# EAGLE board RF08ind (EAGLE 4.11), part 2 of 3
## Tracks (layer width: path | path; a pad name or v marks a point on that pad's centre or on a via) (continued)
DMA02  (via drill 0.61) (continued)
  Top 0.254: DMA0-3.2 25.39,125.56 24.12,126.83 24.12,149.7 25.39,150.97 IC38.4 | v16.51,205.58 2.54,191.61 v2.54,154.78 | v67.31,19.52 v67.31,31.59 | v141.6,16.35 145.41,20.16 145.41,151.6 146.68,152.87 v146.68,206.84
  Bottom 0.254: 146.68,207.48 114.93,207.48 112.39,204.94 80.64,204.94 80.01,205.58 v16.51,205.58 | v2.54,154.78 8.25,149.06 8.88,149.7 15.87,149.7 16.51,150.33 23.49,150.33 24.76,151.6 IC38.4 | v67.31,31.59 65.4,31.59 64.13,32.86 RS08.14 | v67.31,19.52 67.94,20.16 73.66,20.16 74.29,20.79 114.93,20.79 118.11,23.96 128.27,23.96 130.81,21.43 133.34,21.43 138.43,16.35 v141.6,16.35 | 146.68,207.48 v146.68,206.84 | 146.68,207.48 165.73,207.48 167,206.21 IC27.13
DMA03  (via drill 0.61)
  Top 0.254: v29.21,126.2 30.48,127.47 30.48,150.97 IC38.2 | v192.4,91.91 191.77,92.54 189.22,95.08 189.22,154.78 189.86,155.41 189.86,193.51 v198.75,202.4 | v183.51,83.02 v154.3,53.81 | v67.31,44.92 67.31,35.4 66.04,34.12 66.04,33.49 RS08.12 | v20.32,120.48 19.68,119.85 19.68,98.26 15.87,94.45 v15.87,51.27
  Bottom 0.254: v29.21,126.2 24.76,126.2 23.49,124.93 DMA0-3.3 22.86,123.02 v20.32,120.48 | v183.51,83.02 v192.4,91.91 | v154.3,53.81 144.78,44.29 138.43,44.29 137.79,44.92 137.79,51.91 90.17,51.91 83.18,44.92 v67.31,44.92 66.04,44.92 65.4,44.29 34.92,44.29 33.65,45.55 21.59,45.55 v15.87,51.27 | v198.75,202.4 199.38,201.77 212.09,201.77 215.26,204.94 IC39.9
DMA04  (via drill 0.61)
  Top 0.254: v38.73,126.2 38.09,126.83 v38.09,152.24 | RS08.9 68.58,29.68 69.84,28.41 v69.84,11.27 69.84,1.74 142.87,1.74 191.13,50 194.31,53.18 194.31,87.46 v201.93,95.08 | v23.49,121.75 22.22,120.48 22.22,114.77 22.86,114.13 22.86,82.38 20.32,79.84 20.32,25.23 v25.39,20.16 | v212.09,176.37 212.09,203.03 210.81,204.31 IC39.11 | v190.5,99.53 v190.5,154.78
  Bottom 0.254: v38.09,152.24 40,154.14 43.81,154.14 45.08,152.87 IC31.8 | DMA4-7.7 42.54,124.93 41.27,126.2 v38.73,126.2 35.55,123.02 29.21,123.02 27.94,121.75 v23.49,121.75 | v25.39,20.16 29.21,16.35 29.21,11.27 v69.84,11.27 | v190.5,154.78 v212.09,176.37 | v190.5,99.53 194.94,95.08 v201.93,95.08
DMA05  (via drill 0.61)
  Top 0.254: IC31.6 50.79,150.97 52.06,149.7 52.06,144.62 49.52,142.08 49.52,138.27 50.16,137.63 50.16,136.36 46.98,133.19 46.98,126.83 45.71,125.56 DMA4-7.6 45.71,123.02 v45.71,121.12 | 95.25,7.46 147.31,7.46 190.5,50.63 190.5,86.19 193.67,89.37 193.67,91.91 191.77,93.81 191.77,194.15 v200.66,203.03 | 95.25,7.46 v95.25,27.78 | v90.8,3.01 95.25,7.46
  Bottom 0.254: v95.25,27.78 93.98,29.05 67.94,29.05 66.67,30.32 RS08.11 | v45.71,121.12 44.45,119.85 24.12,119.85 23.49,119.21 15.23,119.21 11.42,115.4 7.62,115.4 5.71,113.5 5.71,5.55 39.36,5.55 41.9,3.01 v90.8,3.01 | v200.66,203.03 203.19,203.03 205.1,204.94 IC39.13
DMA06  (via drill 0.61)
  Top 0.254: DMA4-7.2 55.88,125.56 54.6,126.83 54.6,149.7 55.88,150.97 IC31.4 | 188.59,91.27 189.86,92.54 | 188.59,91.27 v170.18,72.86 | v120.01,56.35 116.84,53.18 v116.84,46.83 | v66.04,43.65 64.13,41.74 64.13,36.03 62.22,34.12 62.22,32.22 63.49,30.95 RS08.13 | v23.49,120.48 23.49,81.75 21.59,79.84 v21.59,44.29 | 188.59,91.27 v188.59,185.25
  Bottom 0.254: v170.18,72.86 154.94,57.62 121.28,57.62 v120.01,56.35 | v116.84,46.83 86.99,46.83 83.81,43.65 v66.04,43.65 34.28,43.65 33.02,44.92 22.22,44.92 v21.59,44.29 | v23.49,120.48 27.94,120.48 29.84,122.39 53.97,122.39 55.24,123.66 DMA4-7.2 | v188.59,185.25 187.32,186.53 188.59,187.8 226.69,187.8 241.3,202.4 250.82,202.4 253.36,204.94 IC43.9
DMA07  (via drill 0.61)
  Top 0.254: IC31.2 60.95,150.97 60.95,127.47 v59.68,126.2 59.68,112.23 | v188.59,186.53 187.32,185.25 187.32,91.27 v170.18,74.13 | v129.53,62.06 123.82,62.06 v123.82,72.22 | v80.64,69.68 81.28,70.32 81.28,81.75 80.01,83.02 80.01,108.42 79.37,109.05 79.37,109.69 v80.01,110.32 | v60.32,111.59 59.68,112.23 | 59.68,112.23 59.68,69.68 60.95,68.41 60.95,36.66 59.68,35.4 59.68,32.22 60.95,30.95 RS08.15 | v248.91,201.13 248.91,204.31 IC43.11
  Bottom 0.254: v59.68,126.2 55.24,126.2 53.97,124.93 DMA4-7.3 | v248.91,201.13 234.31,186.53 v188.59,186.53 | v170.18,74.13 150.49,74.13 140.97,64.6 135.88,64.6 133.34,62.06 v129.53,62.06 | v123.82,72.22 121.28,74.77 118.11,74.77 113.03,69.68 v80.64,69.68 | v80.01,110.32 78.73,111.59 v60.32,111.59
DMA08  (via drill 0.61)
  Top 0.254: v67.94,126.2 68.58,126.83 68.58,138.27 67.31,139.53 67.31,140.17 67.94,140.81 v67.94,151.6 67.94,159.22 72.39,163.67 72.39,200.5 v74.93,203.03 | v57.14,53.81 57.14,32.22 58.41,30.95 RS08.17 | v78.1,55.08 78.73,55.72 78.73,93.81 77.47,95.08 73.02,95.08 73.02,112.86 72.39,113.5 72.39,119.85 73.66,121.12 73.66,123.02 DMA8-11.7
  Bottom 0.254: v67.94,126.2 71.75,126.2 73.02,124.93 DMA8-11.7 | v67.94,151.6 70.48,154.14 74.29,154.14 75.56,152.87 IC24.8 | v74.93,203.03 80.01,203.03 80.64,203.67 180.97,203.67 184.78,207.48 241.93,207.48 243.2,206.21 IC43.13 | v57.14,53.81 59.05,55.72 77.47,55.72 v78.1,55.08
DMA09  (via drill 0.61)
  Top 0.254: 82.55,130.65 76.83,124.93 DMA8-11.6 | 82.55,130.65 82.55,149.7 81.28,150.97 IC24.6 81.28,153.5 80.01,154.78 v80.01,204.31 | v159.38,202.4 v156.84,204.94 | v54.6,45.55 54.6,32.22 55.88,30.95 RS08.19 | v76.2,46.83 82.55,53.18 82.55,87.46 81.91,88.1 81.91,110.96 82.55,111.59 82.55,130.65 | v194.94,202.4 204.47,211.93 204.47,214.47 201.93,217 201.93,220.81 287.01,220.81 293.37,214.47 293.37,208.12 292.1,206.84 IC45.9
  Bottom 0.254: v156.84,204.94 156.21,204.31 v80.01,204.31 | v54.6,45.55 55.88,46.83 v76.2,46.83 | v194.94,202.4 v159.38,202.4
DMA10  (via drill 0.61)
  Top 0.254: 85.09,149.7 85.09,126.83 86.36,125.56 DMA8-11.2 86.36,123.02 83.81,120.48 83.81,110.32 83.18,109.69 83.18,89.37 83.81,88.73 83.81,49.37 v85.09,48.09 | 85.09,149.7 86.36,150.97 IC24.4 | v97.15,210.66 85.09,198.59 85.09,149.7 | v52.06,45.55 52.06,32.22 53.34,30.95 RS08.21
  Bottom 0.254: v52.06,45.55 54.6,48.09 v85.09,48.09 | v97.15,210.66 103.5,210.66 105.41,208.75 283.84,208.75 286.38,206.21 IC45.11
DMA11  (via drill 0.61)
  Top 0.254: v97.79,128.11 97.15,128.74 97.15,153.5 v97.79,154.14 97.79,163.03 100.96,166.21 100.96,183.35 100.33,183.99 v100.33,199.86 | v81.28,25.23 81.28,50.63 83.18,52.54 83.18,88.1 82.55,88.73 82.55,110.32 83.18,110.96 83.18,123.66 DMA8-11.3 | v284.48,201.13 284.48,201.77 281.94,204.31 IC45.13
  Bottom 0.254: v97.79,128.11 87.62,128.11 84.45,124.93 DMA8-11.3 | v97.79,154.14 93.34,154.14 92.07,152.87 IC24.2 | v284.48,201.13 267.33,183.99 188.59,183.99 172.08,200.5 151.12,200.5 150.49,201.13 147.95,201.13 147.31,200.5 100.96,200.5 v100.33,199.86 | v81.28,25.23 76.2,25.23 74.29,27.14 61.59,27.14 59.68,29.05 59.68,30.95 59.05,31.59 52.7,31.59 51.43,30.32 RS08.23
DMA-IN\  (via drill 0.61)
  Top 0.254: IC26.1 78.73,16.35 78.73,18.89 76.2,21.43 IC26.19 76.2,23.96 72.39,27.78 v72.39,37.94 | IC41.12 18.41,85.56 19.68,84.29 19.68,16.35 29.84,6.18 44.45,6.18 44.45,10.63 45.08,11.27 48.25,11.27 48.25,13.81 IC34.1
  Bottom 0.254: IC34.1 48.89,14.44 50.16,13.17 76.83,13.17 78.1,14.44 IC26.1 | v72.39,37.94 102.87,37.94 IC13.4
DMA-OUT\
  Top 0.254: IC35.1 45.71,72.22 43.17,74.77 43.17,77.3 IC35.19
  Bottom 0.254: IC28.19 70.48,77.94 69.21,76.67 45.08,76.67 43.81,77.94 IC35.19 42.54,79.21 41.27,80.48 22.86,80.48 22.86,88.73 18.41,93.18 IC41.9 | IC28.1 73.02,70.32 71.75,69.05 47.62,69.05 46.35,70.32 IC35.1
DONE  (via drill 0.61)
  Top 0.254: v3.81,143.98 3.81,191.61 v19.05,206.84 | v112.39,206.21 125.73,192.88 125.73,176.37 125.09,175.73 125.09,174.46 126.36,173.19 IC11.9 | v280.67,122.39 280.67,93.81 281.94,92.54 IC46.13
  Bottom 0.254: v3.81,143.98 4.44,143.34 12.69,143.34 14.6,141.44 20.95,141.44 22.22,140.17 IC40.2 | v19.05,206.84 19.68,206.21 v112.39,206.21 | v280.67,122.39 252.09,150.97 168.27,150.97 160.65,158.59 158.75,158.59 146.05,171.28 129.53,171.28 128.27,172.56 IC11.9
DRV01\  (via drill 0.61)
  Top 0.254: v18.41,38.57 13.33,43.65 13.33,80.48 10.79,83.02 IC41.4
  Bottom 0.254: v18.41,38.57 19.05,39.2 26.03,39.2 32.38,32.86 RS08.38
DRV23\  (via drill 0.61)
  Top 0.254: v14.6,66.51 14.6,86.83 10.79,90.64 IC41.7 | v50.79,62.06 53.34,59.52 53.34,33.49 RS08.22
  Bottom 0.254: v14.6,66.51 19.05,62.06 v50.79,62.06
DRVOK\  (via drill 0.61)
  Top 0.254: IC21.13 95.88,80.48 95.88,79.21 IC21.14 97.15,77.94 98.42,76.67 98.42,56.35 97.15,55.08 v97.15,45.55 | v30.48,43.65 30.48,33.49 RS08.40
  Bottom 0.254: R2.1 25.39,37.3 29.84,32.86 RS08.40 | v97.15,45.55 93.98,42.38 48.89,42.38 48.25,43.02 31.11,43.02 v30.48,43.65
EIE  (via drill 0.61)
  Top 0.254: IC40.9 12.69,148.43 11.42,149.7 11.42,173.83 14.6,177 INTENB.6 | v93.34,105.24 92.7,105.88 92.7,133.82 v93.34,134.46
  Bottom 0.254: v93.34,105.24 128.27,105.24 130.81,102.7 133.34,102.7 138.43,97.62 140.97,97.62 144.14,94.45 169.54,94.45 172.08,91.91 IC33.11 | v93.34,134.46 8.88,134.46 1.9,141.44 1.9,148.43 8.88,148.43 9.52,149.06 10.79,149.06 12.06,147.79 IC40.9 | IC37.2 32.38,187.16 29.21,183.99 13.96,183.99 13.33,183.35 13.33,178.27 14.6,178.27 INTENB.6
ERROR  (via drill 0.61)
  Top 0.254: v36.82,173.83 v36.82,145.25 | v95.88,173.83 96.52,174.46 v96.52,183.99 | v127,182.72 128.9,180.81 128.9,163.03 131.44,160.49 IC7.2
  Bottom 0.254: v36.82,145.25 17.14,145.25 15.87,146.52 IC40.10 | v95.88,173.83 v36.82,173.83 | v96.52,183.99 97.15,184.62 103.5,184.62 106.04,187.16 IC12.6 107.31,187.16 111.12,183.35 126.36,183.35 v127,182.72
EXAD0\
  Top 0.254: IC20.9 88.9,13.81 84.45,9.36 84.45,6.82 83.18,5.55 71.12,5.55 71.12,6.82 C35L.34
EXAD1\
  Top 0.254: IC20.7 93.34,15.71 92.07,16.98 83.81,16.98 83.81,7.46 82.55,6.18 73.66,6.18 73.66,6.82 C35L.36
EXAD2\
  Bottom 0.254: IC20.5 98.42,14.44 92.7,8.73 78.1,8.73 76.83,7.46 C35L.38
F.1  (via drill 0.61)
  Top 0.254: IC20.11 86.99,22.06 88.26,20.79 92.7,20.79 92.7,47.46 92.07,48.09 92.07,93.81 94.61,96.35 94.61,99.53 95.25,100.16 99.06,100.16 99.06,126.2 100.33,127.47 100.33,138.9 100.96,139.53 100.96,151.6 101.59,152.24 v101.59,185.89 v101.59,213.83 | v49.52,192.24 49.52,190.34 48.25,189.06 IC30.8 | v86.36,192.88 88.9,190.34 88.9,189.06 FIELD.3
  Bottom 0.254: v101.59,185.89 90.8,185.89 89.53,187.16 FIELD.3 | v49.52,192.24 50.16,192.88 v86.36,192.88 | v101.59,213.83 144.78,213.83 146.05,215.1 173.35,215.1 174.62,213.83 IC27.5
F.2  (via drill 0.61)
  Top 0.254: 90.17,185.25 90.17,150.97 91.44,149.7 91.44,23.96 IC20.13 | 90.17,185.25 91.44,186.53 FIELD.2 | 90.17,185.25 v90.17,197.32 90.17,202.4 v99.69,211.93
  Bottom 0.254: v90.17,197.32 45.08,197.32 43.81,196.05 IC30.11 | v99.69,211.93 100.33,211.29 168.27,211.29 169.54,212.56 IC27.3
F.3  (via drill 0.61)
  Top 0.254: v81.28,191.61 81.28,189.06 FIELD.6 | v48.25,190.97 48.25,194.15 IC30.13 | IC20.15 97.15,22.06 102.87,16.35 102.87,13.81 108.58,8.09 146.68,8.09 146.68,101.43 148.59,103.34 148.59,121.75 150.49,123.66 v150.49,199.86 150.49,212.56 164.46,212.56 IC27.1
  Bottom 0.254: v48.25,190.97 49.52,190.97 50.79,192.24 80.64,192.24 v81.28,191.61 93.34,191.61 101.59,199.86 v150.49,199.86
GND  (via drill 0.61)
  Top 0.508: IC4.8 131.44,103.34 131.44,102.07 IC4.7 132.71,100.8 133.98,99.53 133.98,74.13 | IC2.7 131.44,51.27 131.44,52.54 IC2.8 132.71,53.81 133.98,55.08 133.98,74.13 | IC3.8 131.44,77.94 131.44,76.67 IC3.7 132.71,75.4 133.98,74.13 | J14.2 27.94,171.92 27.94,170.65 D34L.1 | J13.2 30.48,171.92 30.48,170.65 D34L.3 | D34L.5 33.02,170.65 33.02,171.92 J12.2 33.02,173.19 34.28,174.46 34.28,182.72 | J11.2 35.55,171.92 35.55,170.65 D34L.7 | J10.2 38.09,171.92 38.09,170.65 D34L.9 | J9.2 40.63,171.92 40.63,170.65 D34L.11 | J8.2 43.17,171.92 43.17,170.65 D34L.13 | J6.2 48.25,171.92 48.25,170.65 D34L.17 | IC37.10 12.69,186.53 12.69,185.25 14.6,183.35 INTENB.8 14.6,182.08 10.15,177.64 10.15,161.12 IC38.11 10.15,158.59 10.15,153.5 IC38.10 10.15,150.97 10.15,150.33 8.88,149.06 8.88,142.08 10.15,140.81 IC40.7 10.15,138.27 8.88,137 8.88,126.83 10.15,125.56 DMA0-3.8 10.15,123.02 10.15,117.31 IC23.7 10.79,116.04 12.06,114.77 12.06,102.07 | INTENB.4 14.6,173.19 14.6,174.46 INTENB.5 | IC37.6 22.86,186.53 22.86,183.35 INTENB.9 | 34.28,182.72 33.65,182.72 C36L.5 | 34.28,182.72 34.92,182.72 C36L.7 | C36L.39 76.2,183.35 76.2,186.53 FIELD.8 76.2,189.06 76.2,194.15 FIELD.9 | IC30.10 43.17,186.53 43.17,183.35 C36L.13 | IC30.6 53.34,186.53 53.34,183.35 C36L.21 | C36L.31 65.4,182.72 64.13,182.72 C36L.29 | IC16.8 104.14,112.23 104.14,118.58 IC17.1 | IC9.7 120.01,124.93 121.28,126.2 121.28,135.09 120.01,136.36 IC10.2 120.01,137.63 121.28,138.9 121.28,147.79 120.01,149.06 IC10.7 | 104.14,173.83 104.14,186.53 IC12.7 | 104.14,173.83 104.14,160.49 IC18.7 | C1.2 139.06,187.8 137.79,187.8 IC8.1 137.16,186.53 137.79,185.89 137.79,161.76 139.06,160.49 IC7.15
  Top 0.508: IC6.8 131.44,150.33 131.44,156.68 IC7.1 132.71,157.95 133.98,159.22 133.98,173.19 132.71,174.46 IC7.8 | 104.14,173.83 118.11,173.83 118.11,175.09 IC11.7 | IC36.8 24.76,109.69 24.12,110.32 24.12,114.77 25.39,116.04 D36L.1 | D36L.7 32.38,116.67 31.11,116.67 D36L.5 | IC32.5 43.81,102.07 45.08,103.34 45.08,107.15 43.81,108.42 IC32.8 42.54,109.69 41.9,110.32 41.9,116.67 | DMA4-7.8 40.63,123.02 40.63,117.31 D36L.13 41.27,116.67 41.9,116.67 | 41.9,116.67 42.54,116.67 D36L.15 | D36L.17 46.35,116.67 47.62,116.67 D36L.19 48.89,116.67 50.16,116.67 D36L.21 50.79,117.31 50.79,123.02 DMA4-7.4 50.79,125.56 52.06,126.83 52.06,137 50.79,138.27 DAR4-7.4 | IC24.10 71.12,150.97 69.84,149.7 69.84,143.34 71.12,142.08 71.12,140.81 DAR8-11.8 | IC31.10 40.63,150.97 41.9,149.7 41.9,144.62 41.27,143.98 41.27,140.17 DAR4-7.8 | DMA8-11.8 71.12,123.02 71.12,117.31 D36L.37 | D36L.25 55.24,116.67 53.97,116.67 D36L.23 | D36L.33 65.4,116.67 64.13,116.67 D36L.31 | v68.58,139.53 69.21,138.9 69.21,116.67 D36L.35 | IC1.7 131.44,25.87 131.44,27.14 IC1.8 130.81,27.78 v127,31.59 | IC20.17 101.59,23.96 103.5,25.87 103.5,29.68 IC13.1 103.5,30.95 103.5,32.22 IC13.2 104.77,33.49 106.04,34.76 106.04,43.65 104.77,44.92 IC13.7 103.5,46.19 103.5,50 IC14.1 103.5,51.27 103.5,52.54 IC14.2 104.77,53.81 106.04,55.08 106.04,56.35 | IC16.1 103.5,93.18 103.5,86.83 IC15.7 104.77,85.56 106.04,84.29 106.04,76.67 | 106.04,56.35 104.77,57.62 IC14.4 | 106.04,63.97 104.77,65.24 IC14.7 | 106.04,63.97 106.04,56.35 | 106.04,76.67 104.77,77.94 IC15.4 | 106.04,76.67 106.04,63.97 | IC26.10 55.88,13.81 55.88,10.63 C35L.21 55.24,10 53.97,10 C35L.19
  Top 0.508: C35L.35 74.29,10 75.56,10 C35L.37 76.83,10 78.1,10 C35L.39 | J2.2 58.41,5.55 57.14,6.82 57.14,8.09 58.41,9.36 C35L.23 | IC34.10 25.39,16.35 26.67,17.62 26.67,25.87 30.48,29.68 RS08.39 30.48,30.95 22.86,38.57 22.86,69.68 IC35.10 22.86,72.22 23.49,72.86 23.49,76.67 24.12,77.3 24.12,84.29 25.39,85.56 D35L.1 26.03,86.19 26.67,86.19 | C35L.5 34.92,10 33.65,10 C35L.3 | RS08.31 40.63,29.68 41.9,28.41 41.9,18.89 39.36,16.35 39.36,11.9 38.09,10.63 C35L.7 | C35L.11 42.54,10 41.27,10 C35L.9 | C35L.15 47.62,10 46.35,10 C35L.13 | 70.48,99.53 71.12,98.89 71.12,86.83 D35L.37 70.48,86.19 69.21,86.19 D35L.35 67.94,86.19 66.67,86.19 D35L.33 | 70.48,99.53 69.21,100.8 IC25.5 | 70.48,99.53 70.48,107.15 69.21,108.42 IC25.8 | 57.78,99.53 58.41,98.89 58.41,86.83 D35L.27 | 57.78,99.53 56.51,100.8 IC29.5 | 57.78,99.53 57.78,107.15 56.51,108.42 IC29.8 57.14,109.05 57.14,114.77 58.41,116.04 D36L.27 | IC22.7 88.26,113.5 86.36,111.59 86.36,93.81 88.26,91.91 IC21.8 89.53,91.91 89.53,93.18 v90.17,93.81 | 12.06,102.07 12.06,95.72 10.79,94.45 IC41.8 | 12.06,102.07 10.79,103.34 IC23.2 | IC36.5 24.76,100.8 24.76,99.53 IC36.4 26.03,98.26 27.94,96.35 27.94,86.83 D35L.3 | 26.67,86.19 27.3,86.19 D35L.3 | D35L.3 28.57,86.19 29.84,86.19 D35L.5 31.11,86.19 32.38,86.19 D35L.7 33.65,86.19 34.92,86.19 D35L.9 36.19,86.19 37.46,86.19 D35L.11 | D35L.19 47.62,86.19 46.35,86.19 D35L.17 | 26.67,86.19 26.67,81.11 27.94,79.84 IC35.13 | v135.88,105.24 135.25,105.88 135.25,121.12 132.71,123.66 IC5.7 | v173.99,197.32 173.99,206.84 179.7,212.56 IC27.7 | v292.1,101.43 292.73,102.07 292.73,177.64 299.08,183.99 300.99,183.99 300.99,205.58 294.63,211.93 IC45.7
  Bottom 0.508: 216.53,100.8 182.24,100.8 180.97,99.53 IC33.7 179.7,99.53 177.8,101.43 151.76,101.43 149.22,103.97 146.05,103.97 144.78,102.7 135.88,102.7 | 216.53,100.8 217.8,99.53 IC42.7 | 254.63,100.8 255.9,99.53 IC44.7 | 254.63,100.8 216.53,100.8 | 254.63,100.8 292.73,100.8 294,99.53 IC46.7 294.63,100.16 293.37,101.43 v292.1,101.43 | 135.88,102.7 134.62,102.7 133.34,103.97 IC4.8 | D34L.1 28.57,170.02 29.84,170.02 D34L.3 31.11,170.02 32.38,170.02 D34L.5 33.65,170.02 34.92,170.02 D34L.7 36.19,170.02 37.46,170.02 D34L.9 38.73,170.02 40,170.02 D34L.11 41.27,170.02 42.54,170.02 D34L.13 43.81,170.02 45.08,170.02 D34L.15 46.35,170.02 47.62,170.02 D34L.17 48.89,170.02 50.16,170.02 D34L.19 51.43,170.02 52.7,170.02 D34L.21 53.97,170.02 55.24,170.02 D34L.23 56.51,170.02 57.78,170.02 D34L.25 59.05,170.02 60.32,170.02 D34L.27 61.59,170.02 62.86,170.02 D34L.29 64.13,170.02 65.4,170.02 D34L.31 66.67,170.02 67.94,170.02 D34L.33 69.21,170.02 70.48,170.02 D34L.35 71.75,170.02 73.02,170.02 D34L.37 74.29,170.02 75.56,170.02 D34L.39 | C36L.5 32.38,182.72 31.11,182.72 C36L.3 29.84,182.72 28.57,182.72 C36L.1 27.3,182.72 24.12,182.72 INTENB.9 22.22,182.08 19.05,178.91 | C36L.7 36.19,182.72 37.46,182.72 C36L.9 38.73,182.72 40,182.72 C36L.11 41.27,182.72 42.54,182.72 C36L.13 43.81,182.72 45.08,182.72 C36L.15 46.35,182.72 47.62,182.72 C36L.17 48.89,182.72 50.16,182.72 C36L.19 51.43,182.72 52.7,182.72 C36L.21 53.97,182.72 55.24,182.72 C36L.23 56.51,182.72 57.78,182.72 C36L.25 59.05,182.72 60.32,182.72 C36L.27 61.59,182.72 62.86,182.72 C36L.29
  Bottom 0.508: 19.05,178.91 15.87,175.73 INTENB.5 | 19.05,178.91 15.87,182.08 INTENB.8 | IC19.7 97.79,182.72 91.44,182.72 86.99,187.16 FIELD.4 85.72,187.16 84.45,187.16 FIELD.5 83.18,187.16 78.73,182.72 76.83,182.72 C36L.39 75.56,182.72 74.29,182.72 C36L.37 73.02,182.72 71.75,182.72 C36L.35 70.48,182.72 69.21,182.72 C36L.33 67.94,182.72 66.67,182.72 C36L.31 | IC17.8 105.41,137 106.68,138.27 116.84,138.27 118.11,137 IC10.2 120.01,137.63 121.92,139.53 125.73,139.53 IC10.12 | IC9.12 125.73,114.13 123.19,114.13 120.65,111.59 IC9.2 118.11,111.59 116.84,112.86 106.68,112.86 105.41,111.59 IC16.8 | IC5.7 130.81,124.29 129.53,125.56 121.92,125.56 120.65,124.29 IC9.7 118.11,124.29 115.56,124.29 113.03,121.75 IC17.15 110.48,121.75 107.95,121.75 105.41,119.21 IC17.1 102.87,119.21 87.62,119.21 84.45,122.39 79.37,122.39 | IC11.7 120.65,175.09 121.92,176.37 129.53,176.37 130.81,175.09 IC7.8 | IC10.7 120.65,149.7 121.92,150.97 129.53,150.97 130.81,149.7 IC6.8 | IC7.1 133.34,157.31 135.88,159.86 138.43,159.86 IC7.15 | D36L.1 26.03,116.67 27.3,116.67 D36L.3 28.57,116.67 29.84,116.67 D36L.5 | D36L.7 33.65,116.67 34.92,116.67 D36L.9 36.19,116.67 37.46,116.67 D36L.11 38.73,116.67 40,116.67 D36L.13 | D36L.17 45.08,116.67 43.81,116.67 D36L.15 | DAR8-11.4 80.64,140.17 79.37,141.44 73.02,141.44 71.75,140.17 DAR8-11.8 70.48,139.53 v68.58,139.53 | DAR4-7.8 41.27,140.17 42.54,141.44 48.89,141.44 50.16,140.17 DAR4-7.4 | 79.37,122.39 80.64,123.66 DMA8-11.4 | 79.37,122.39 73.02,122.39 71.75,123.66 DMA8-11.8 | D36L.39 73.02,116.67 71.75,116.67 D36L.37 70.48,116.67 69.21,116.67 D36L.35 67.94,116.67 66.67,116.67 D36L.33
  Bottom 0.508: D36L.23 52.7,116.67 51.43,116.67 D36L.21 | D36L.25 56.51,116.67 57.78,116.67 D36L.27 59.05,116.67 60.32,116.67 D36L.29 61.59,116.67 62.86,116.67 D36L.31 | v127,31.59 106.68,31.59 105.41,32.86 IC13.2 | IC16.15 110.48,96.35 107.95,93.81 105.41,93.81 IC16.1 102.87,93.81 v90.17,93.81 | IC14.13 110.48,53.18 105.41,53.18 IC14.2 | IC20.10 85.72,14.44 81.28,10 79.37,10 C35L.39 | C35L.21 56.51,10 57.78,10 C35L.23 59.05,10 60.32,10 C35L.25 61.59,10 62.86,10 C35L.27 64.13,10 65.4,10 C35L.29 66.67,10 67.94,10 C35L.31 69.21,10 70.48,10 C35L.33 71.75,10 73.02,10 C35L.35 | IC34.10 25.39,13.81 29.21,10 29.84,10 C35L.1 31.11,10 32.38,10 C35L.3 | C35L.5 36.19,10 37.46,10 C35L.7 38.73,10 40,10 C35L.9 | C35L.13 45.08,10 43.81,10 C35L.11 | C35L.15 48.89,10 50.16,10 C35L.17 51.43,10 52.7,10 C35L.19 | D35L.33 65.4,86.19 64.13,86.19 D35L.31 62.86,86.19 61.59,86.19 D35L.29 60.32,86.19 59.05,86.19 D35L.27 57.78,86.19 56.51,86.19 D35L.25 55.24,86.19 53.97,86.19 D35L.23 52.7,86.19 51.43,86.19 D35L.21 50.16,86.19 48.89,86.19 D35L.19 | IC21.8 87.62,91.27 86.99,90.64 78.73,90.64 74.29,86.19 D35L.39 73.02,86.19 71.75,86.19 D35L.37 | 13.33,161.76 14.6,160.49 IC38.13 | 13.33,161.76 12.06,161.76 10.79,160.49 IC38.11 | 18.41,161.76 19.68,160.49 IC38.15 | 13.33,161.76 18.41,161.76 | 18.41,161.76 23.49,161.76 24.76,160.49 IC38.17 | DMA0-3.4 19.68,124.93 18.41,126.2 12.06,126.2 10.79,124.93 DMA0-3.8 | 31.11,76.67 29.84,76.67 28.57,77.94 IC35.13 | 31.11,76.67 32.38,77.94 IC35.15 | 31.11,76.67 36.19,76.67 37.46,77.94 IC35.17 | IC28.10 50.16,71.59 48.89,72.86 24.76,72.86 23.49,71.59 IC35.10
  Bottom 0.508: D35L.11 38.73,86.19 40,86.19 D35L.13 41.27,86.19 42.54,86.19 D35L.15 43.81,86.19 45.08,86.19 D35L.17 | IC23.2 11.42,103.97 16.51,98.89 24.12,98.89 IC36.4 | v173.99,197.32 164.46,187.8 140.33,187.8 C1.2 | 135.88,102.7 v135.88,105.24 | 254.63,215.1 220.34,215.1 219.07,213.83 IC39.7 | 254.63,215.1 255.9,213.83 IC43.7 | 254.63,215.1 292.73,215.1 294,213.83 IC45.7
INT_RQ\  (via drill 0.61)
  Top 0.254: IC40.6 12.69,140.81 10.15,143.34 10.15,145.89 IC40.8 | v64.77,162.4 64.13,163.03 64.13,166.21 63.49,166.84 D34L.30 | v35.55,143.98 v35.55,164.3
  Bottom 0.254: IC40.3 19.68,138.9 18.41,137.63 14.6,137.63 13.33,138.9 IC40.6 | v64.77,162.4 46.98,162.4 45.08,164.3 v35.55,164.3 | v35.55,143.98 34.92,144.62 12.69,144.62 10.79,146.52 IC40.8
IOS\  (via drill 0.61)
  Top 0.254: v101.59,109.05 102.87,110.32 106.68,110.32 v106.68,109.05 | v143.5,106.52 144.78,107.78 144.78,152.24 v145.41,152.87 | v120.65,152.24 114.3,158.59 114.3,163.67 v109.22,168.75
  Bottom 0.254: v101.59,109.05 97.79,109.05 IC22.10 | v106.68,109.05 107.95,107.78 128.27,107.78 129.53,106.52 v143.5,106.52 | v145.41,152.87 144.78,152.24 v120.65,152.24 | v109.22,168.75 62.86,168.75 61.59,167.47 D34L.28
MYDEV\
  Top 0.254: IC32.4 42.54,99.53 38.09,103.97 38.09,108.42 PAD1.1
  Bottom 0.254: IC25.4 67.31,98.89 66.04,97.62 58.41,97.62 57.14,98.89 IC29.4 54.6,98.89 53.34,98.89 52.06,97.62 45.71,97.62 44.45,98.89 IC32.4
N$1
  Top 0.254: IC36.9 34.28,109.05 34.92,109.05 PAD8.1
N$2
  Top 0.254: IC10.8 126.36,150.33 125.09,151.6 125.09,165.57 126.36,166.84 IC11.11
N$3  (via drill 0.61)
  Top 0.254: v48.25,126.83 48.25,130.65 DMA4-7.12
  Bottom 0.254: v48.25,126.83 43.17,126.83 42.54,127.47 21.59,127.47 21.59,123.02 20.95,122.39 19.68,122.39 18.41,123.66 DMA0-3.5
N$4  (via drill 0.61)
  Top 0.254: SW1.1 118.74,10.63 118.74,11.9 SW1.2 118.74,13.17 118.74,14.44 SW1.3 118.74,15.71 118.74,16.98 SW1.4 118.74,18.25 118.74,19.52 SW1.5 118.74,20.79 118.74,22.06 SW1.6 118.74,23.33 118.74,24.6 SW1.7 118.74,25.87 118.74,27.14 SW1.8 | v93.98,81.11 94.61,81.75 94.61,91.91 95.25,92.54 100.33,92.54 100.33,34.76 102.23,32.86 v102.23,27.78
  Bottom 0.254: v93.98,81.11 90.17,81.11 IC21.4 | v102.23,27.78 118.11,27.78 SW1.8
N$5
  Top 0.254: IC36.15 34.28,93.81 34.92,93.81 PAD2.1
N$6
  Top 0.254: IC36.14 34.28,96.35 34.92,96.35 PAD3.1
N$7
  Top 0.254: IC36.13 34.28,98.89 34.92,98.89 PAD4.1
N$8
  Top 0.254: IC36.12 34.28,101.43 34.92,101.43 PAD5.1
N$9
  Top 0.254: IC36.11 34.28,103.97 34.92,103.97 PAD6.1
N$10
  Top 0.254: IC36.10 34.28,106.52 34.92,106.52 PAD7.1
N$11  (via drill 0.61)
  Top 0.254: v30.48,109.05 33.02,111.59 34.92,111.59 PAD9.1
  Bottom 0.254: v30.48,109.05 29.21,109.05 26.67,106.52 IC36.7
N$12  (via drill 0.61)
  Top 0.254: v106.04,145.89 106.04,160.49 104.77,161.76 104.77,168.75 107.95,168.75 108.58,168.11 108.58,163.03 111.12,160.49 IC18.8
  Bottom 0.254: 81.91,145.25 55.24,145.25 53.97,146.52 DAR4-7.14 | 81.91,145.25 83.18,146.52 DAR8-11.14 | v106.04,145.89 90.17,145.89 89.53,145.25 81.91,145.25
N$13  (via drill 0.61)
  Top 0.254: v76.83,128.74 78.73,130.65 DMA8-11.12
  Bottom 0.254: v76.83,128.74 76.2,129.38 64.77,129.38 62.86,127.47 51.43,127.47 48.89,124.93 DMA4-7.5
N$14  (via drill 0.61)
  Top 0.254: v114.93,45.55 114.3,46.19 114.3,63.34 112.39,65.24 IC14.8 111.12,66.51 111.12,68.41 107.95,71.59 107.95,83.02 v107.31,83.65
  Bottom 0.254: v114.93,45.55 113.03,45.55 IC13.8 | v107.31,83.65 105.41,83.65 IC15.6
N$15
  Top 0.254: IC2.5 132.71,46.19 134.62,48.09 134.62,109.05 132.71,110.96 IC5.2
N$16  (via drill 0.61)
  Top 0.254: v21.59,135.72 18.41,132.55 DMA0-3.12
  Bottom 0.254: v21.59,135.72 46.98,135.72 48.89,137.63 63.49,137.63 64.13,138.27 69.84,138.27 70.48,137.63 76.83,137.63 78.1,138.9 DAR8-11.5
N$17  (via drill 0.61)
  Top 0.254: SW2.1 118.74,36.03 118.74,37.3 SW2.2 118.74,38.57 118.74,39.84 SW2.3 118.74,41.11 118.74,42.38 SW2.4 118.74,43.65 118.74,44.92 SW2.5 118.74,46.19 118.74,47.46 SW2.6 118.74,48.73 118.74,50 SW2.7 118.74,51.27 118.74,52.54 SW2.8 | v93.34,83.65 92.7,83.02 92.7,51.27 v93.34,50.63
  Bottom 0.254: v93.34,83.65 90.17,83.65 IC21.5 | v93.34,50.63 95.88,48.09 118.11,48.09 SW2.6
N$18
  Top 0.254: R3.1 160.02,178.27 160.02,182.08 LED1.A
N$19  (via drill 0.61)
  Top 0.254: SW3.1 118.74,61.43 118.74,62.7 SW3.2 118.74,63.97 118.74,65.24 SW3.3 118.74,66.51 118.74,67.78 SW3.4 118.74,69.05 118.74,70.32 SW3.5 118.74,71.59 118.74,72.86 SW3.6 118.74,74.13 118.74,75.4 SW3.7 118.74,76.67 118.74,77.94 SW3.8 118.74,79.21 118.74,80.48 v114.3,84.92
  Bottom 0.254: v114.3,84.92 91.44,84.92 90.17,86.19 IC21.6
N$20
  Top 0.254: SW4.1 118.74,86.83 118.74,88.1 SW4.2 118.74,89.37 118.74,90.64 SW4.3 118.74,91.91 118.74,93.18 SW4.4 118.74,94.45 118.74,95.72 SW4.5 118.74,96.99 118.74,98.26 SW4.6 118.74,99.53 118.74,100.8 SW4.7 118.74,102.07 118.74,103.34 SW4.8
  Bottom 0.254: IC21.7 90.17,88.73 91.44,87.46 116.84,87.46 118.11,88.73 SW4.2
N$21
  Top 0.254: IC3.5 131.44,71.59 130.17,72.86 130.17,114.77 131.44,116.04 IC5.4
N$22  (via drill 0.61)
  Top 0.254: v101.59,138.9 101.59,148.43 102.23,149.06 102.23,155.41 103.5,156.68 IC18.6
  Bottom 0.254: 51.43,130.01 24.76,130.01 23.49,131.28 DMA0-3.14 | 51.43,130.01 52.7,131.28 DMA4-7.14 | 81.91,130.01 83.18,131.28 DMA8-11.14 | 81.91,130.01 51.43,130.01 | v101.59,138.9 92.7,130.01 81.91,130.01
N$23  (via drill 0.61)
  Top 0.254: v135.25,30.95 135.25,23.33 132.71,20.79 IC1.5 | v144.14,32.22 v144.14,103.97
  Bottom 0.254: v135.25,30.95 136.52,32.22 v144.14,32.22 | v144.14,103.97 145.41,105.24 145.41,107.78 143.5,107.78 140.97,110.32 134.62,110.32 133.34,109.05 IC5.1
N$24  (via drill 0.61)
  Top 0.254: v125.09,97.62 125.09,104.61 129.53,109.05 129.53,116.67 131.44,118.58 IC5.5
  Bottom 0.254: v125.09,97.62 129.53,97.62 130.81,96.35 IC4.5
N$25  (via drill 0.61)
  Top 0.254: v48.89,136.36 48.89,137.63 48.25,138.27 DAR4-7.5 | v64.13,137 64.77,136.36 v64.77,128.11 | v74.93,128.11 77.47,130.65 v77.47,137 | v80.01,137.63 80.01,144.62 78.73,145.89 DAR8-11.12
  Bottom 0.254: v48.89,136.36 49.52,137 v64.13,137 | v64.77,128.11 65.4,128.74 74.29,128.74 v74.93,128.11 | v77.47,137 78.1,137.63 v80.01,137.63
N$26  (via drill 0.61)
  Top 0.254: v113.66,100.16 113.66,104.61 112.39,105.88 IC16.11
  Bottom 0.254: v113.66,100.16 91.44,100.16 90.17,98.89 IC22.1
N$27  (via drill 0.61)
  Top 0.254: v98.42,126.83 98.42,108.42 97.15,107.15 IC22.11
  Bottom 0.254: v98.42,126.83 102.87,126.83 IC17.4
N$28
  Bottom 0.254: IC19.1 100.33,167.47 101.59,166.21 129.53,166.21 130.81,167.47 IC7.5
N$29
  Top 0.254: RA.2 125.09,197.96 126.36,197.96 RB.1
  Bottom 0.254: IC8.7 133.98,196.05 130.81,199.22 128.9,199.22 127.63,197.96 RB.1
N$30
  Top 0.254: IC12.2 117.47,187.16 118.74,187.16 IC12.1
  Bottom 0.254: 132.71,185.89 133.34,185.25 133.98,185.25 RL.2 | 132.71,185.89 132.08,186.53 IC8.3 | 132.71,185.89 125.73,185.89 125.09,186.53 120.65,186.53 120.01,187.16 IC12.1
N$31
  Bottom 0.254: IC18.11 113.03,152.24 116.84,148.43 121.92,148.43 125.73,144.62 IC10.10
N$32
  Top 0.254: IC8.2 135.25,188.43 139.06,192.24 139.06,192.88 C1.1 | RB.2 127,188.43 132.08,193.51 132.08,194.15 IC8.6
  Bottom 0.254: IC8.2 134.62,189.06 134.62,193.51 133.98,193.51 132.71,194.78 IC8.6
N$33
  Bottom 0.254: IC19.11 107.95,175.09 109.22,173.83 120.65,173.83 125.73,168.75 137.16,168.75 138.43,167.47 IC7.12
N$34
  Top 0.254: IC8.5 129.53,196.69 129.53,197.32 C2.2
N$35
  Top 0.254: R4.1 172.72,178.27 172.72,182.08 LED2.A
N$36
  Top 0.254: LED3.A 185.41,182.08 185.41,178.27 R5.1
N$37
  Top 0.254: IC12.9 107.31,194.78 108.58,194.78 IC12.10 109.85,194.78 111.12,194.78 IC12.11
N$38
  Top 0.254: LED4.A 198.12,182.08 198.12,178.27 R6.1
N$39
  Top 0.254: LED5.A 210.81,182.08 210.81,178.27 R7.1
N$40
  Top 0.254: IC12.5 109.22,189.06 104.14,194.15 IC12.8
N$41
  Top 0.254: LED6.A 223.52,182.08 223.52,178.27 R8.1
N$42
  Top 0.254: LED7.A 236.22,182.08 236.22,178.27 R9.1
N$43
  Top 0.254: LED8.A 248.91,182.08 248.91,178.27 R10.1
N$44
  Top 0.254: LED9.A 261.62,182.08 261.62,178.27 R11.1
N$45
  Top 0.254: R12.1 274.31,178.27 276.86,180.81 276.86,182.08 LED10.A
N$46
  Top 0.254: LED11.A 287.01,182.08 287.01,178.27 R13.1
N$47
  Top 0.254: LED12.A 299.72,182.08 299.72,178.27 R14.1
N$48
  Top 0.254: R15.1 160.02,152.87 160.02,156.68 LED13.A
N$49
  Top 0.254: R16.1 172.72,152.87 172.72,156.68 LED14.A
N$50
  Top 0.254: R17.1 185.41,152.87 185.41,156.68 LED15.A
N$51
  Top 0.254: R18.1 198.12,152.87 198.12,156.68 LED16.A
N$52
  Top 0.254: R19.1 210.81,152.87 210.81,156.68 LED17.A
N$53
  Top 0.254: SW1.16 126.36,10.63 125.09,11.9 125.09,15.71 125.73,16.35 130.81,16.35 130.81,17.62 IC1.4
N$54
  Bottom 0.254: SW1.15 128.27,12.54 130.81,15.08 IC1.3
N$55
  Top 0.254: SW1.14 128.27,15.08 130.81,12.54 IC1.2
N$56
  Bottom 0.254: IC1.1 130.81,10 129.53,11.27 125.73,11.27 125.09,11.9 125.09,17.62 125.73,17.62 SW1.13
N$57
  Bottom 0.254: SW1.11 127.63,22.06 130.81,18.89 134.62,18.89 138.43,15.08 IC1.14
N$58
  Bottom 0.254: SW1.10 128.27,25.23 129.53,23.96 133.34,23.96 139.06,18.25 IC1.13
N$59
  Bottom 0.254: SW1.9 128.27,27.78 129.53,26.51 133.34,26.51 139.06,20.79 IC1.12
N$60
  Bottom 0.254: SW1.12 127.63,19.52 130.81,16.35 134.62,16.35 138.43,12.54 IC1.15
N$61
  Top 0.254: SW2.16 126.36,36.03 125.09,37.3 125.09,41.11 125.73,41.74 130.81,41.74 130.81,43.02 IC2.4
N$62
  Bottom 0.254: SW2.15 128.27,37.94 130.81,40.48 IC2.3
N$63
  Top 0.254: SW2.14 128.27,40.48 130.81,37.94 IC2.2
N$64
  Bottom 0.254: IC2.1 130.81,35.4 129.53,36.66 125.73,36.66 125.09,37.3 125.09,43.02 125.73,43.02 SW2.13
N$65
  Bottom 0.254: SW2.11 127.63,47.46 130.81,44.29 133.98,44.29 137.79,40.48 138.43,40.48 IC2.14
N$66
  Bottom 0.254: SW2.10 128.27,50.63 129.53,49.37 133.34,49.37 137.16,45.55 137.16,43.65 139.06,43.65 IC2.13
N$67
  Bottom 0.254: SW2.9 128.27,53.18 129.53,54.45 140.97,54.45 144.14,51.27 144.14,45.55 140.97,45.55 IC2.12
N$68
  Bottom 0.254: SW3.16 127.63,61.43 130.81,64.6 133.34,64.6 133.98,65.24 133.98,67.78 132.71,67.78 IC3.4
N$69
  Bottom 0.254: SW3.15 128.27,63.34 130.81,65.88 IC3.3
N$70
  Top 0.254: SW3.14 128.27,65.88 130.81,63.34 IC3.2
N$71
  Top 0.254: IC3.1 131.44,61.43 128.27,64.6 125.09,64.6 125.09,66.51 126.36,67.78 SW3.13
N$72
  Bottom 0.254: SW3.11 127.63,72.86 130.81,69.68 134.62,69.68 138.43,65.88 IC3.14
N$73
  Bottom 0.254: SW3.10 127.63,75.4 130.81,72.22 134.62,72.22 138.43,68.41 IC3.13
N$74
  Bottom 0.254: SW3.9 127.63,77.94 130.81,74.77 134.62,74.77 138.43,70.95 IC3.12
N$75
  Bottom 0.254: SW4.16 128.27,86.19 129.53,87.46 133.34,87.46 133.98,88.1 133.98,93.18 132.71,93.18 IC4.4
N$76
  Bottom 0.254: SW4.15 128.27,88.73 130.81,91.27 IC4.3
N$77
  Bottom 0.254: SW4.14 126.36,90.64 125.09,89.37 125.09,87.46 128.27,87.46 129.53,88.73 130.81,88.73 IC4.2
N$78
  Bottom 0.254: IC4.1 130.81,86.19 129.53,84.92 125.73,84.92 124.45,86.19 124.45,93.81 125.73,93.81 SW4.13
N$79  (via drill 0.61)
  Top 0.254: v128.9,95.08 128.9,96.99 127.63,98.26 SW4.11
  Bottom 0.254: v128.9,95.08 134.62,95.08 138.43,91.27 IC4.14
N$80
  Bottom 0.254: SW4.10 127.63,100.8 130.81,97.62 134.62,97.62 138.43,93.81 IC4.13
N$81
  Bottom 0.254: SW4.9 127.63,103.34 130.81,100.16 134.62,100.16 138.43,96.35 IC4.12
N$82
  Bottom 0.254: SW4.12 125.73,96.35 123.82,94.45 123.82,84.29 133.98,84.29 138.43,88.73 IC4.15
N$83
  Bottom 0.254: SW3.12 126.36,70.32 125.09,69.05 125.09,59.52 134.62,59.52 138.43,63.34 IC3.15
N$84
  Bottom 0.254: SW2.12 127.63,44.92 130.81,41.74 133.34,41.74 137.16,37.94 138.43,37.94 IC2.15
N$85
  Top 0.254: R20.1 223.52,152.87 223.52,156.68 LED18.A
N$86
  Top 0.254: R21.1 236.22,152.87 236.22,156.68 LED19.A
N$87
  Top 0.254: R22.1 248.91,152.87 248.91,156.68 LED20.A
N$88
  Top 0.254: R23.1 261.62,152.87 261.62,156.68 LED21.A
N$89
  Top 0.254: R24.1 274.31,152.87 274.31,156.68 LED22.A
N$90
  Top 0.254: R25.1 287.01,152.87 287.01,156.68 LED23.A
N$91
  Top 0.254: R26.1 299.72,152.87 299.72,156.68 LED24.A
N$92
  Top 0.254: LED25.A 160.02,131.28 160.02,127.47 R27.1
N$93
  Top 0.254: LED26.A 172.72,131.28 172.72,127.47 R28.1
N$94
  Top 0.254: LED27.A 185.41,131.28 185.41,127.47 R29.1
N$95
  Top 0.254: LED28.A 198.12,131.28 198.12,127.47 R30.1
N$96
  Top 0.254: LED29.A 210.81,131.28 210.81,127.47 R31.1
N$97
  Top 0.254: LED30.A 223.52,131.28 223.52,127.47 R32.1
N$98
  Top 0.254: LED31.A 236.22,131.28 236.22,127.47 R33.1
N$99
  Top 0.254: LED32.A 248.91,131.28 248.91,127.47 R34.1
N$100
  Top 0.254: LED33.A 261.62,131.28 261.62,127.47 R35.1
N$101
  Top 0.254: LED34.A 274.31,131.28 274.31,127.47 R36.1
N$102
  Top 0.254: LED35.A 287.01,131.28 287.01,127.47 R37.1
N$103
  Top 0.254: LED36.A 299.72,131.28 299.72,127.47 R38.1
N$104
  Top 0.254: R39.1 160.02,104.61 160.02,109.05 LED37.A
N$105
  Top 0.254: R40.1 172.72,104.61 172.72,109.05 LED38.A
N$106
  Top 0.254: R41.1 185.41,104.61 185.41,109.05 LED39.A
N$107
  Top 0.254: R42.1 198.12,104.61 198.12,109.05 LED40.A
N$108
  Top 0.254: R43.1 210.81,104.61 210.81,109.05 LED41.A
N$109
  Top 0.254: R44.1 223.52,104.61 223.52,109.05 LED42.A
N$110
  Top 0.254: R45.1 236.22,104.61 236.22,109.05 LED43.A
N$111
  Top 0.254: R46.1 248.91,104.61 248.91,109.05 LED44.A
N$112
  Top 0.254: R47.1 261.62,104.61 261.62,109.05 LED45.A
N$113
  Top 0.254: R48.1 274.31,104.61 274.31,109.05 LED46.A
N$114
  Top 0.254: R49.1 287.01,104.61 287.01,109.05 LED47.A
N$115
  Top 0.254: R50.1 299.72,104.61 299.72,109.05 LED48.A
N$116
  Top 0.254: LED40.K 197.48,111.59 193.67,111.59 PAD10.1
N$117
  Top 0.254: LED1.K 160.02,185.89 163.83,189.7 163.83,208.12 167.63,211.93 IC27.2
N$118
  Top 0.254: LED2.K 172.72,185.89 171.44,187.16 171.44,210.66 172.72,211.93 IC27.4
N$119
  Top 0.254: LED3.K 185.41,185.89 181.61,189.7 181.61,215.1 179.7,215.1 178.43,213.83 IC27.6
N$120  (via drill 0.61)
  Top 0.254: v177.16,177.64 180.34,180.81 180.34,204.31 IC27.8
  Bottom 0.254: v177.16,177.64 160.02,160.49 LED13.K
N$121
  Top 0.254: LED14.K 172.72,160.49 175.25,163.03 175.25,204.31 IC27.10
N$122
  Top 0.254: LED15.K 184.78,159.86 173.99,159.86 173.99,159.22 173.35,158.59 171.44,158.59 171.44,185.89 170.18,187.16 170.18,204.31 IC27.12
N$123
  Top 0.254: IC33.2 167.63,100.16 161.92,105.88 161.92,131.92 160.02,133.82 LED25.K
N$124
  Top 0.254: LED26.K 172.72,133.82 171.44,132.55 171.44,101.43 172.72,100.16 IC33.4
N$125
  Top 0.254: IC33.6 177.8,100.16 181.61,103.97 181.61,130.01 185.41,133.82 LED27.K
N$126  (via drill 0.61)
  Top 0.254: v165.73,95.72 161.28,100.16 161.28,110.96 160.65,111.59 LED37.K
  Bottom 0.254: v165.73,95.72 175.89,95.72 179.7,91.91 IC33.8
N$127
  Top 0.254: IC33.10 175.25,92.54 173.99,93.81 173.99,110.96 173.35,111.59 LED38.K
N$128
  Top 0.254: IC33.12 170.81,90.64 172.08,89.37 184.15,89.37 184.15,110.96 184.78,111.59 LED39.K
N$129
  Top 0.254: LED43.K 235.58,111.59 231.77,111.59 PAD11.1
N$130
  Top 0.254: LED5.K 210.81,185.89 209.55,187.16 209.55,210.66 210.81,211.93 IC39.4
N$131
  Top 0.254: LED6.K 223.52,185.89 219.71,189.7 219.71,208.12 215.9,211.93 IC39.6
N$132
  Top 0.254: LED16.K 198.75,159.86 207.64,150.97 224.78,150.97 224.78,171.92 218.44,178.27 218.44,204.31 IC39.8
N$133
  Top 0.254: LED17.K 210.81,160.49 213.36,163.03 213.36,204.31 IC39.10
N$134
  Top 0.254: LED18.K 222.88,159.86 212.09,159.86 212.09,159.22 211.45,158.59 209.55,158.59 209.55,185.89 208.28,187.16 208.28,204.31 IC39.12
N$135
  Top 0.254: IC42.2 205.74,100.16 205.1,100.8 205.1,126.83 198.12,133.82 LED28.K
N$136
  Top 0.254: LED29.K 210.81,133.82 209.55,132.55 209.55,101.43 210.81,100.16 IC42.4
N$137
  Top 0.254: IC42.6 215.9,100.16 219.07,103.34 219.07,129.38 223.52,133.82 LED30.K
N$138
  Top 0.254: LED4.K 198.12,185.89 201.93,189.7 201.93,208.12 205.74,211.93 IC39.2
N$139
  Top 0.254: IC42.10 213.36,92.54 212.09,93.81 212.09,110.96 211.45,111.59 LED41.K
N$140
  Top 0.254: IC42.12 208.91,90.64 210.18,89.37 219.71,89.37 219.71,108.42 222.88,111.59 LED42.K
N$141
  Top 0.254: LED7.K 236.22,185.89 240.03,189.7 242.56,192.24 242.56,210.66 243.84,211.93 IC43.2
N$142
  Top 0.254: LED8.K 248.91,185.89 247.65,187.16 247.65,210.66 248.91,211.93 IC43.4
N$143
  Top 0.254: LED9.K 261.62,185.89 257.81,189.7 257.81,208.12 254,211.93 IC43.6
N$144
  Top 0.254: LED19.K 236.85,159.86 245.74,150.97 262.88,150.97 262.88,171.92 256.54,178.27 256.54,204.31 IC43.8
N$145
  Top 0.254: LED20.K 248.91,160.49 251.46,163.03 251.46,204.31 IC43.10
N$146
  Top 0.254: LED21.K 260.98,159.86 250.19,159.86 250.19,159.22 249.55,158.59 247.65,158.59 247.65,185.89 246.38,187.16 246.38,204.31 IC43.12
N$147
  Top 0.254: IC44.2 243.84,100.16 237.49,106.52 237.49,132.55 236.22,133.82 LED31.K
N$148
  Top 0.254: LED32.K 248.91,133.82 247.65,132.55 247.65,101.43 248.91,100.16 IC44.4
N$149
  Top 0.254: IC44.6 254,100.16 257.81,103.97 257.81,130.01 261.62,133.82 LED33.K
N$151
  Top 0.254: IC44.10 251.46,92.54 250.19,93.81 250.19,110.96 249.55,111.59 LED44.K
N$152
  Top 0.254: IC44.12 247.01,90.64 248.28,89.37 260.35,89.37 260.35,110.96 260.98,111.59 LED45.K
N$153
  Top 0.254: LED10.K 276.86,185.89 278.12,187.16 280.67,189.7 280.67,210.66 281.94,211.93 IC45.2
N$154
  Top 0.254: LED11.K 287.01,185.89 288.29,187.16 288.29,210.66 287.01,211.93 IC45.4
N$155
  Top 0.254: LED12.K 299.72,185.89 295.91,189.7 290.82,194.78 290.82,210.66 292.1,211.93 IC45.6
N$156
  Bottom 0.254: LED22.K 274.95,159.86 291.46,176.37 297.81,176.37 298.44,177 298.44,204.31 295.91,204.31 295.27,204.94 IC45.8
N$157
  Top 0.254: LED23.K 287.01,160.49 289.56,163.03 289.56,204.31 IC45.10
N$158
  Top 0.254: 293.37,166.84 299.72,160.49 LED24.K
  Bottom 0.254: IC45.12 285.11,204.94 286.38,203.67 292.73,203.67 293.37,204.31 293.37,207.48 296.54,207.48 300.99,203.03 300.99,160.49 299.72,160.49 LED24.K
N$159
  Top 0.254: IC46.2 281.94,100.16 281.94,126.2 274.31,133.82 LED34.K
N$160
  Top 0.254: LED35.K 287.01,133.82 285.75,132.55 285.75,101.43 287.01,100.16 IC46.4
N$161
  Top 0.254: IC46.6 292.1,100.16 295.91,103.97 295.91,130.01 299.72,133.82 LED36.K
N$162
  Bottom 0.254: IC46.8 295.27,91.91 306.06,102.7 310.51,102.7 311.14,103.34 311.14,107.15 279.39,107.15 274.95,111.59 LED46.K
N$163
  Top 0.254: IC46.10 289.56,92.54 288.29,93.81 288.29,110.96 287.65,111.59 LED47.K
N$164
  Top 0.254: IC46.12 285.11,90.64 286.38,89.37 298.44,89.37 298.44,110.96 299.08,111.59 LED48.K
NXD  (via drill 0.61)
  Top 0.254: v239.39,95.72 226.69,108.42 v226.69,189.06 | IC30.4 58.41,189.06 59.68,190.34 59.68,197.32 v62.22,199.86 62.22,210.02 11.42,210.02 1.27,199.86 1.27,137 v5.71,132.55 | v14.6,112.86 15.87,114.13 15.87,119.85 v16.51,120.48
  Bottom 0.254: v239.39,95.72 243.2,91.91 IC44.13 | v226.69,189.06 214.62,201.13 151.76,201.13 151.12,201.77 147.31,201.77 146.68,201.13 66.04,201.13 65.4,200.5 62.86,200.5 v62.22,199.86 | v14.6,112.86 12.69,112.86 11.42,111.59 IC23.5 | v16.51,120.48 15.87,119.85 8.88,119.85 6.98,121.75 6.98,132.55 v5.71,132.55
NXD\  (via drill 0.61)
  Top 0.254: v30.48,118.58 31.75,119.85 v31.75,137 | v3.81,142.71 5.08,143.98 5.08,173.19 4.44,173.83 4.44,190.97 v22.22,208.75 | v104.14,208.75 114.3,198.59 114.3,196.69 IC12.12
  Bottom 0.254: v30.48,118.58 15.87,118.58 11.42,114.13 IC23.6 | v31.75,137 24.76,143.98 5.71,143.98 4.44,145.25 3.81,145.25 2.54,143.98 2.54,142.71 v3.81,142.71 | v104.14,208.75 v22.22,208.75
PBIT
  Bottom 0.254: IC35.11 22.22,79.21 19.05,82.38 8.88,82.38 7.62,81.11 7.62,60.8 100.33,60.8 102.87,63.34 IC14.6
PCA  (via drill 0.61)
  Top 0.254: v6.98,178.27 v6.98,142.08
  Bottom 0.254: v6.98,142.08 12.69,142.08 14.6,140.17 IC40.5 | v6.98,178.27 14.6,185.89 15.87,185.89 17.14,187.16 IC37.8 18.41,188.43 19.68,189.7 112.39,189.7 113.66,188.43 IC12.3
PER  (via drill 0.61)
  Top 0.254: v283.2,108.42 283.2,96.35 287.01,92.54 IC46.11 | v66.04,185.25 64.13,187.16 IC30.2 | v74.29,188.43 74.93,189.06 74.93,200.5 92.07,217.64 148.59,217.64 v148.59,123.02
  Bottom 0.254: v283.2,108.42 268.6,123.02 v148.59,123.02 129.53,123.02 128.27,121.75 IC9.9 | v66.04,185.25 69.21,188.43 v74.29,188.43
PER\  (via drill 0.61)
  Top 0.254: v127,183.99 134.62,176.37 v134.62,130.65 | v127.63,130.01 127.63,124.93 IC9.8
  Bottom 0.254: v127,183.99 115.56,183.99 112.39,187.16 IC12.4 | v134.62,130.65 133.98,130.01 v127.63,130.01
PIE  (via drill 0.61)
  Top 0.254: IC40.4 17.78,140.81 19.05,142.08 v19.05,163.67 20.32,164.94 20.32,182.72 21.59,183.99 21.59,199.86 55.24,199.86 57.14,197.96 | 57.14,197.96 58.41,196.69 IC30.17 | v154.3,202.4 154.3,105.88 167.63,92.54 IC33.13 | 57.14,197.96 v60.32,201.13
  Bottom 0.254: v19.05,163.67 15.87,166.84 INTENB.2 | v154.3,202.4 75.56,202.4 74.93,201.77 65.4,201.77 64.77,201.13 v60.32,201.13
PROTECT
  Top 0.254: IC5.6 131.44,122.39 130.17,123.66 130.17,135.09 131.44,136.36 IC6.3
SETNXD\  (via drill 0.61)
  Top 0.254: v99.06,55.72 99.06,88.73 97.15,90.64 IC21.9
  Bottom 0.254: v99.06,55.72 98.42,56.35 58.41,56.35 57.78,55.72 6.98,55.72 6.98,105.88 9.52,108.42 IC23.4
SETPER\  (via drill 0.61)
  Top 0.254: v102.23,49.37 102.23,42.38 103.5,41.11 IC13.5 | v121.28,49.37 121.28,117.94 v122.55,119.21
  Bottom 0.254: v102.23,49.37 v121.28,49.37 | v122.55,119.21 125.73,119.21 IC9.10
SETWLS\  (via drill 0.61)
  Top 0.254: v130.17,120.48 129.53,121.12 129.53,144.62 131.44,146.52 IC6.7
  Bottom 0.254: v130.17,120.48 117.47,120.48 117.47,118.58 118.74,117.31 IC9.4
SKIP\  (via drill 0.61)
  Top 0.254: 97.15,168.11 97.15,166.21 96.52,165.57 R1.1 96.52,164.3 96.52,124.93 v97.15,124.29 | 97.15,168.11 98.42,169.38 IC19.2 | 97.15,168.11 97.15,178.27 98.42,179.54 IC19.6
  Bottom 0.254: IC19.10 105.41,177.64 102.87,180.18 100.33,180.18 IC19.6 | v97.15,124.29 100.33,124.29 102.87,121.75 IC17.2
START\  (via drill 0.61)
  Top 0.254: v102.87,141.44 102.23,142.08 102.23,147.79 103.5,149.06 IC18.3
  Bottom 0.254: 43.81,133.82 17.14,133.82 15.87,132.55 DMA0-3.11 | 43.81,133.82 45.08,132.55 DMA4-7.11 | 74.29,133.82 75.56,132.55 DMA8-11.11 | 74.29,133.82 43.81,133.82 | v102.87,141.44 94.61,133.19 90.17,133.19 89.53,133.82 74.29,133.82
VCC  (via drill 0.61)
  Top 0.508: R38.2 309.88,126.2 309.88,104.61 R50.2 | 241.3,93.81 241.3,92.54 IC44.14 | 241.3,93.81 241.3,95.72 233.68,103.34 R44.2 | 241.3,93.81 245.11,97.62 245.11,102.07 246.38,103.34 R45.2 246.38,104.61 246.38,126.2 R33.2 | R34.2 259.07,126.2 259.07,104.61 R46.2 | R3.2 169.54,177.64 169.54,199.86 165.09,204.31 IC27.14 | R6.2 207.64,177.64 207.64,199.86 203.19,204.31 IC39.14 | 309.88,165.57 309.88,152.87 R26.2 | 309.88,165.57 309.88,177 R14.2 | 309.88,165.57 297.81,177.64 R13.2 | 59.68,144.62 59.68,134.46 58.41,133.19 DMA4-7.16 | 59.68,144.62 58.41,145.89 DAR4-7.16 | 59.68,144.62 59.68,154.14 60.95,154.14 62.86,156.05 62.86,157.95 63.49,158.59 IC31.20 63.49,161.12 62.22,162.4 62.22,170.65 v60.95,171.92 62.22,173.19 v62.22,190.97 | v64.77,202.4 66.04,201.13 66.04,196.69 IC30.20 66.04,194.15 v66.04,190.97 | RA.1 124.45,187.16 124.45,185.89 RL.1 124.45,184.62 124.45,172.56 126.36,170.65 IC11.10 125.73,170.02 v124.45,168.75 | IC8.4 130.17,188.43 136.52,194.78 IC8.8 136.52,196.05 136.52,196.69 135.25,197.96 C2.1 | v99.06,194.78 94.61,194.78 FIELD.16 | IC20.20 109.22,23.96 111.12,25.87 111.12,29.68 IC13.14 111.12,30.95 107.31,34.76 107.31,50 v107.95,50.63 107.95,70.32 v107.31,70.95 | IC22.14 97.15,98.26 102.23,93.18 v102.23,92.54 102.23,77.94 103.5,76.67 IC15.3 103.5,75.4 102.23,74.13 102.23,53.81 | IC26.20 78.73,23.96 80.01,25.23 80.01,30.95 78.73,32.22 RS08.2 | 102.23,53.81 103.5,55.08 IC14.3 | 102.23,53.81 100.96,52.54 100.96,38.57 103.5,36.03 IC13.3 | v44.45,74.77 45.71,76.03 45.71,77.3 IC35.20 45.08,79.21 41.9,82.38 41.9,86.83 37.46,91.27 34.28,91.27 IC36.16 32.38,91.91 31.11,93.18 31.11,98.26 v30.48,98.89
  Top 0.508: IC28.20 73.66,79.84 75.56,81.75 75.56,90.64 IC25.16 | 109.22,118.58 v108.58,119.21 | 109.22,118.58 109.22,96.35 111.12,94.45 IC16.16 | 109.22,118.58 109.22,140.81 v108.58,141.44 109.22,142.08 109.22,161.12 106.68,163.67 106.68,164.3 R1.2 106.68,165.57 106.68,166.84 IC19.14 | v31.11,164.3 31.11,163.03 33.02,161.12 IC38.20 33.02,158.59 31.75,157.31 v31.75,147.79 | v27.94,146.52 27.94,133.19 DMA0-3.16 | DMA8-11.16 88.9,133.19 90.17,134.46 90.17,144.62 88.9,145.89 DAR8-11.16 | v92.7,147.79 92.7,155.41 93.98,156.68 93.98,158.59 IC24.20 | 137.16,85.56 137.16,106.52 137.79,107.15 | 137.16,85.56 137.16,60.8 v136.52,60.16 136.52,13.17 139.06,10.63 IC1.16 | 137.79,107.15 139.06,108.42 IC5.14 | 137.79,130.01 139.06,131.28 IC6.16 | 137.79,130.01 137.79,107.15 | 137.16,85.56 v136.52,85.56 | 137.79,130.01 137.79,155.41 139.06,156.68 IC7.16 | IC43.14 241.3,204.31 233.68,196.69 233.68,178.27 R8.2 | IC45.14 279.39,204.31 271.77,196.69 271.77,178.27 R11.2
  Bottom 0.508: 180.97,128.11 172.08,128.11 170.81,126.83 R27.2 169.54,126.83 163.19,133.19 137.16,133.19 | 180.97,128.11 182.24,126.83 R28.2 | 180.97,128.11 193.67,128.11 194.94,126.83 R29.2 196.21,126.83 197.48,125.56 206.37,125.56 | 206.37,125.56 207.64,126.83 R30.2 | 219.07,125.56 220.34,126.83 R31.2 | 206.37,125.56 219.07,125.56 | 231.77,125.56 233.04,126.83 R32.2 | 219.07,125.56 231.77,125.56 | 231.77,125.56 244.47,125.56 245.74,126.83 R33.2 | 295.27,128.11 286.38,128.11 285.11,126.83 R36.2 | 295.27,128.11 296.54,126.83 R37.2 | 297.18,128.11 295.27,128.11 | 297.18,128.11 307.97,128.11 309.24,126.83 R38.2 | 297.18,102.7 297.18,103.34 R49.2 297.81,103.97 299.08,105.24 307.97,105.24 309.24,103.97 R50.2 | 297.18,102.7 297.18,98.89 295.27,96.99 285.11,96.99 280.03,91.91 IC46.14 | 297.18,102.7 286.38,102.7 285.11,103.97 R48.2 283.84,103.97 282.57,105.24 269.87,105.24 | 180.97,105.24 172.08,105.24 170.81,103.97 R39.2 | 180.97,105.24 182.24,103.97 R40.2 | 193.67,105.24 194.94,103.97 R41.2 | 193.67,105.24 180.97,105.24 | 206.37,105.24 207.64,103.97 R42.2 | 206.37,105.24 193.67,105.24 | 206.37,105.24 219.07,105.24 220.34,103.97 R43.2 221.61,103.97 222.88,102.7 231.77,102.7 233.04,103.97 R44.2 | R34.2 259.71,126.83 260.98,128.11 269.87,128.11 271.14,126.83 R35.2 | IC42.14 203.83,90.64 205.1,89.37 239.39,89.37 240.66,90.64 IC44.14 | 257.17,105.24 258.44,103.97 R46.2 | 257.17,105.24 248.28,105.24 247.01,103.97 R45.2 | 269.87,105.24 271.14,103.97 R47.2 | 257.17,105.24 269.87,105.24 | 180.97,178.91 172.08,178.91 170.81,177.64 R3.2 | 180.97,178.91 182.24,177.64 R4.2 | 193.67,178.91 194.94,177.64 R5.2
  Bottom 0.508: 193.67,178.91 180.97,178.91 | 206.37,178.91 207.64,177.64 R6.2 | 206.37,178.91 193.67,178.91 | 219.07,178.91 220.34,177.64 R7.2 | 219.07,178.91 206.37,178.91 | 231.77,178.91 233.04,177.64 R8.2 | 231.77,178.91 219.07,178.91 | 244.47,178.91 245.74,177.64 R9.2 | 244.47,178.91 231.77,178.91 | 257.17,178.91 258.44,177.64 R10.2 | 257.17,178.91 244.47,178.91 | 269.87,178.91 271.14,177.64 R11.2 | 269.87,178.91 257.17,178.91 | 282.57,178.91 283.84,177.64 R12.2 | 282.57,178.91 269.87,178.91 | 282.57,178.91 295.27,178.91 296.54,177.64 R13.2 | 180.97,153.5 172.08,153.5 170.81,152.24 R15.2 | 180.97,153.5 182.24,152.24 R16.2 | 193.67,153.5 194.94,152.24 R17.2 | 193.67,153.5 180.97,153.5 | 206.37,153.5 207.64,152.24 R18.2 | 206.37,153.5 193.67,153.5 | 219.07,153.5 220.34,152.24 R19.2 | 219.07,153.5 206.37,153.5 | 231.77,153.5 233.04,152.24 R20.2 | 231.77,153.5 219.07,153.5 | 244.47,153.5 245.74,152.24 R21.2 | 244.47,153.5 231.77,153.5 | 257.17,153.5 258.44,152.24 R22.2 | 257.17,153.5 244.47,153.5 | 269.87,153.5 271.14,152.24 R23.2 | 269.87,153.5 257.17,153.5 | 282.57,153.5 283.84,152.24 R24.2 | 282.57,153.5 269.87,153.5 | 295.27,153.5 296.54,152.24 R25.2 297.18,151.6 297.18,128.11 | 295.27,153.5 282.57,153.5 | 295.27,153.5 307.97,153.5 309.24,152.24 R26.2 | J7.2 46.35,172.56 47.62,171.28 51.43,171.28 52.7,172.56 J5.2 53.97,172.56 55.24,172.56 J4.2 56.51,172.56 57.78,172.56 J3.2 59.05,172.56 59.68,171.92 v60.95,171.92 | v64.77,202.4 41.27,202.4 35.55,196.69 IC37.20 | 127.63,189.7 122.55,194.78 120.01,194.78 IC12.14 118.74,194.78 117.47,193.51 100.33,193.51 v99.06,194.78 94.61,190.34 66.67,190.34 v66.04,190.97 v62.22,190.97
  Bottom 0.508: 127.63,189.7 128.9,188.43 IC8.4 | 127.63,189.7 127,189.7 125.09,187.8 RA.1 | v107.95,50.63 110.48,50.63 IC14.14 | v107.31,70.95 110.48,70.95 IC15.14 | IC21.16 97.79,73.49 100.33,76.03 102.87,76.03 IC15.3 | R2.2 26.03,27.78 29.21,24.6 46.35,24.6 47.62,23.33 IC34.20 48.25,23.96 48.25,26.51 73.66,26.51 75.56,24.6 76.83,24.6 78.1,23.33 IC26.20 | 97.79,32.22 80.01,32.22 79.37,32.86 RS08.2 | 97.79,32.22 99.06,33.49 99.06,35.4 102.87,35.4 IC13.3 | 97.79,32.22 100.33,32.22 100.96,31.59 105.41,31.59 106.68,30.32 110.48,30.32 IC13.14 | v44.45,74.77 20.32,74.77 19.05,76.03 IC41.16 | IC23.14 19.05,101.43 21.59,103.97 24.12,103.97 IC36.6 26.03,103.34 v30.48,98.89 | IC36.16 34.28,91.27 35.55,92.54 48.25,92.54 49.52,91.27 IC32.16 52.06,91.27 53.34,91.27 54.6,92.54 57.14,92.54 58.41,91.27 62.22,91.27 IC29.16 64.77,91.27 65.4,91.91 66.67,91.91 67.31,92.54 73.66,92.54 | 73.66,92.54 74.93,91.27 IC25.16 | 73.66,92.54 v102.23,92.54 109.22,92.54 110.48,93.81 IC16.16 | v108.58,119.21 110.48,119.21 IC17.16 | v108.58,141.44 111.12,143.98 IC18.14 | v31.11,164.3 30.48,164.94 24.12,164.94 INTENB.16 | IC40.14 26.03,146.52 v27.94,146.52 30.48,146.52 v31.75,147.79 33.02,146.52 38.73,146.52 40,145.25 41.27,145.25 41.9,145.89 41.9,149.7 86.36,149.7 88.26,147.79 DAR8-11.16 89.53,147.79 v92.7,147.79 | IC7.16 138.43,157.31 137.16,156.05 130.81,156.05 127.63,159.22 IC11.14 125.73,159.86 124.45,158.59 116.2,158.59 112.39,162.4 | 112.39,162.4 111.76,161.76 95.88,161.76 94.61,160.49 IC24.20 | 112.39,162.4 112.39,164.3 106.68,164.3 R1.2 | IC19.14 107.95,167.47 118.11,167.47 IC11.4 120.65,167.47 123.19,167.47 v124.45,168.75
